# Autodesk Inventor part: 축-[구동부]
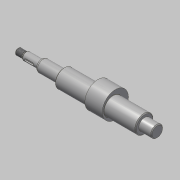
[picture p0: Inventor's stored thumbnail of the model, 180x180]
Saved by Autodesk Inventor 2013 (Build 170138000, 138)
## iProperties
Created: 2015-12
Part Number: 축-[구동부]
Document SubType Name: Modeling
Designer: mdu
Density: 7.86 g/cm^3
Material: 강철, 연강
Mass: 484.681 g
Surface Area: 125.968 cm^2
Volume: 61.6642 cm^3
Author: mdu
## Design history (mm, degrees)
sketch "스케치1"
  geometry: L1 (62, 100.9)-(62, 67.1) reference; L2 (51, 101.2)-(51, 84) reference; L3 (-51, 84)-(-51, 101.2) reference; L4 (-62, 67.1)-(-62, 100.9) reference; L5 (-51.6, 91.5)-(-61.4, 91.5) reference; L6 (51.6, 91.5)-(61.4, 91.5) reference; L7 (67, 84)-(-109, 84); L8 (-77, 64.201)-(-77, 103.799) reference; L9 (67, 84)-(67, 91.5); L10 (67, 91.5)-(51, 91.5); L11 (51, 91.5)-(51, 95.5); L12 (51, 95.5)-(-51, 95.5); L13 (-51, 95.5)-(-51, 91.5); L14 (-51, 91.5)-(-79, 91.5); L15 (-79, 91.5)-(-79, 89); L16 (-79, 89)-(-99, 89); L17 (-99, 89)-(-99, 87); L18 (-100.5, 88)-(-109, 88); L19 (-109, 88)-(-109, 84); L20 (-99, 87)-(-100.5, 87); L21 (-100.5, 87)-(-100.5, 88); 2 further points
  constraints: 32 end point, 7 parallel, 6 point on line, 5 perpendicular, 2 collinear, 2 horizontal, 1 midpoint, 4 other
  dimensions: "d0" = 5 distance from line of L7.start L1; "d2" = 2 distance between parallel lines of L15 L8; "d3" = 23 diameter of L12 L7; "d4" = 10 diameter of L16 L7; "d5" = 1.5 distance of L17.end L20.end; "d6" = 6 diameter of L20 L7; "d7" = 20 distance of L15.end L16.end; "d8" = 10 distance between parallel lines of L17 L19; "d9" = 8 diameter of L18 L7
revolve "회전1" sketch "스케치1" stored, may be unused: angle "d10" = 90 deg
sketch "스케치2"
  geometry: C1 r 11.5 at (84, 0) reference; C2 r 11.5 at (84, 0) reference; C3 r 16.5 at (87, 0); 1 further point
  constraints: 1 centre point, 1 horizontal alignment
  dimensions: "d11" = 33 diameter of C3; "d12" = 3 distance of C3.centre C1.centre
extrude "돌출1" join sketch "스케치2" stored distance "d13" = 22; taper "d14" = 0 deg
chamfer "모따기1" distance "d15" = 1; stored, may be unused: second distance "d16" = 2, angle "d17" = 45 deg
feature "스레드1" dims "d18" = 10, "d19" = 0
node "작업 평면1"
sketch "스케치3"
  geometry: L1 (-5.5, -1.5)-(3.5, -1.5); L2 (3.5, 1.5)-(-5.5, 1.5); L3 (-10, -4)-(-10, 4) reference; A1 r 1.5 centre (3.5, 0) between (3.5, -1.5) and (3.5, 1.5); A2 r 1.5 centre (-5.5, 0) between (-5.5, 1.5) and (-5.5, -1.5); 2 further points
  constraints: 4 end point, 4 point on circle, 4 tangent, 2 centre point, 1 horizontal, 1 horizontal alignment, 1 midpoint, 1 parallel
  dimensions: "d20" = 3 distance between parallel lines of L1 L2; "d21" = 12 dimension on A1 A2; "d22" = 3 distance edge to line of A2 L3
extrude "돌출2" cut sketch "스케치3" distance "d23" = 1.8; taper "d24" = 0 deg
fillet "모깎기1" dims "d25" = 0.3
fillet "모깎기2" dims "d26" = 3
node "솔리드1"
node "참조1"
node "참조2"
node "참조3"
node "참조4"
node "참조5"
node "투영된 루프1"
